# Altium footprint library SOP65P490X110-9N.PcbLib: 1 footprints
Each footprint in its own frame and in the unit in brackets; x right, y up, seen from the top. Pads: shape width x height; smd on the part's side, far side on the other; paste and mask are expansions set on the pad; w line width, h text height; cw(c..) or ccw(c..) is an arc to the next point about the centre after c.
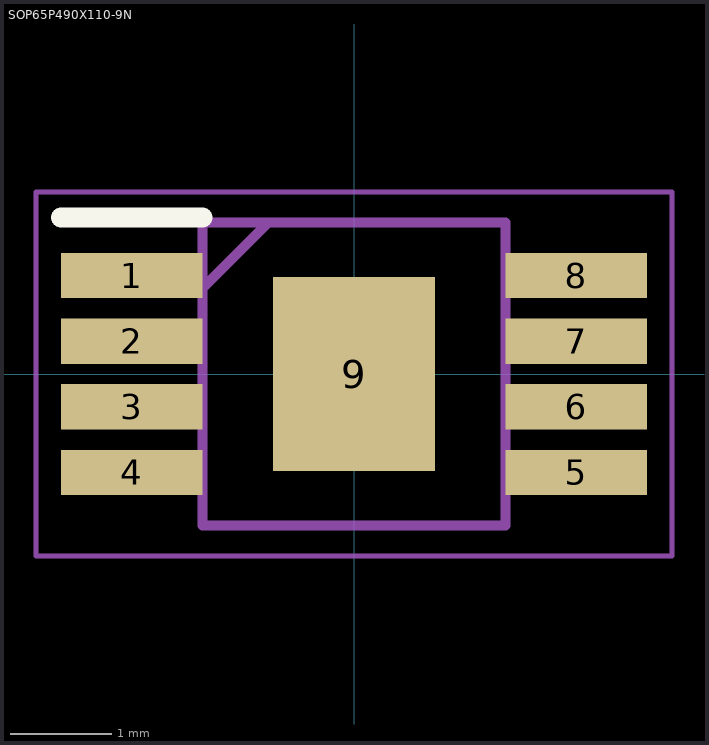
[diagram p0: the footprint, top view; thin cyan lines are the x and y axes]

## SOP65P490X110-9N [mm]
pads (9):
  rect 1.4x0.45 smd: 1(-2.2,0.975) 2(-2.2,0.325) 3(-2.2,-0.325) 4(-2.2,-0.975) 5(2.2,-0.975) 6(2.2,-0.325) 7(2.2,0.325) 8(2.2,0.975)
  rect 1.6x1.92 smd: 9(0,0)
Top Overlay:
  lines w0.2: -2.9,1.55 -1.5,1.55
Mechanical 15:
  lines w0.1: -1.5,0.85 -0.85,1.5 ; -1.5,-1.5 1.5,-1.5 1.5,1.5 -1.5,1.5 -1.5,-1.5
Mechanical 20:
  lines w0.05: -3.15,-1.8 3.15,-1.8 3.15,1.8 -3.15,1.8 -3.15,-1.8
